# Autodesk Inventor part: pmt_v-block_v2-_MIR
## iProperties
Shininess: 64.0
Length Units: 11272
Angle Units: 11279
Time Units: 11290
Mass Units: 11286
Length Display Precision: 3
Angle Display Precision: 2
Compacted: True
Part Number: pmt_v-block_v2-_MIR
Document SubType Name: Modeling
Created: 2004-08
Designer: John Blackburn
Material: Aluminum-6061
Manufacturer: Standard
Standards Organization: Custom
Density: 0.0
Volumn: 0.0
Area: 0.0
PropertySet Name: Model Information
Control State: 0
Master: False
Checked Out: False
Author: John Blackburn
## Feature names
1. Derived Body1 [Tagging]
